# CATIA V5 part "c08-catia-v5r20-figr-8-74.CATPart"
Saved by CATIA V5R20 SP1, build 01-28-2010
Part number: Part1
Bounding box of the stored display mesh (mm): x -48 to 48, y -106.879 to 106.685, z -32.702 to 29.91
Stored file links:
  D:\v5_r20\psrt_files_downloaded\c08-catia-v5r20-prt\c08-catia-v5r20-figr-8-74.CATPart
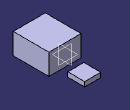
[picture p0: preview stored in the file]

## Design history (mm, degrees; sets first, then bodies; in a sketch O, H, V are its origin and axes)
Body1 (main body)
  Sketch1 on yz-plane, origin (0, 0, 0), H (0, 1, 0), V (0, 0, 1)
    line L1 (-106.8789, 29.9101) -> (0, 29.9101)
    line L2 (0, 29.9101) -> (0, -32.7018)
    line L3 (0, -32.7018) -> (-106.8789, -32.7018)
    line L4 (-106.8789, -32.7018) -> (-106.8789, 29.9101)
    point P3 (0, -32.7018)
    horizontal: L1 H, L3 H
    vertical: L2 V, L4 V
    coincidence: P3 V
  Pad1: profile Sketch1, direction (1, 0, 0), length 48, mirrored extent
  Sketch2 on yz-plane, origin (0, 0, 0), H (0, 1, 0), V (0, 0, 1)
    line L1 (56.3417, 7.481) -> (106.6854, 7.481)
    line L2 (106.6854, 7.481) -> (106.6854, -6.5572)
    line L3 (106.6854, -6.5572) -> (56.3417, -6.5572)
    line L4 (56.3417, -6.5572) -> (56.3417, 7.481)
    horizontal: L1 H, L3 H
    vertical: L2 V, L4 V
  Pad2: profile Sketch2, direction (1, 0, 0), length 48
